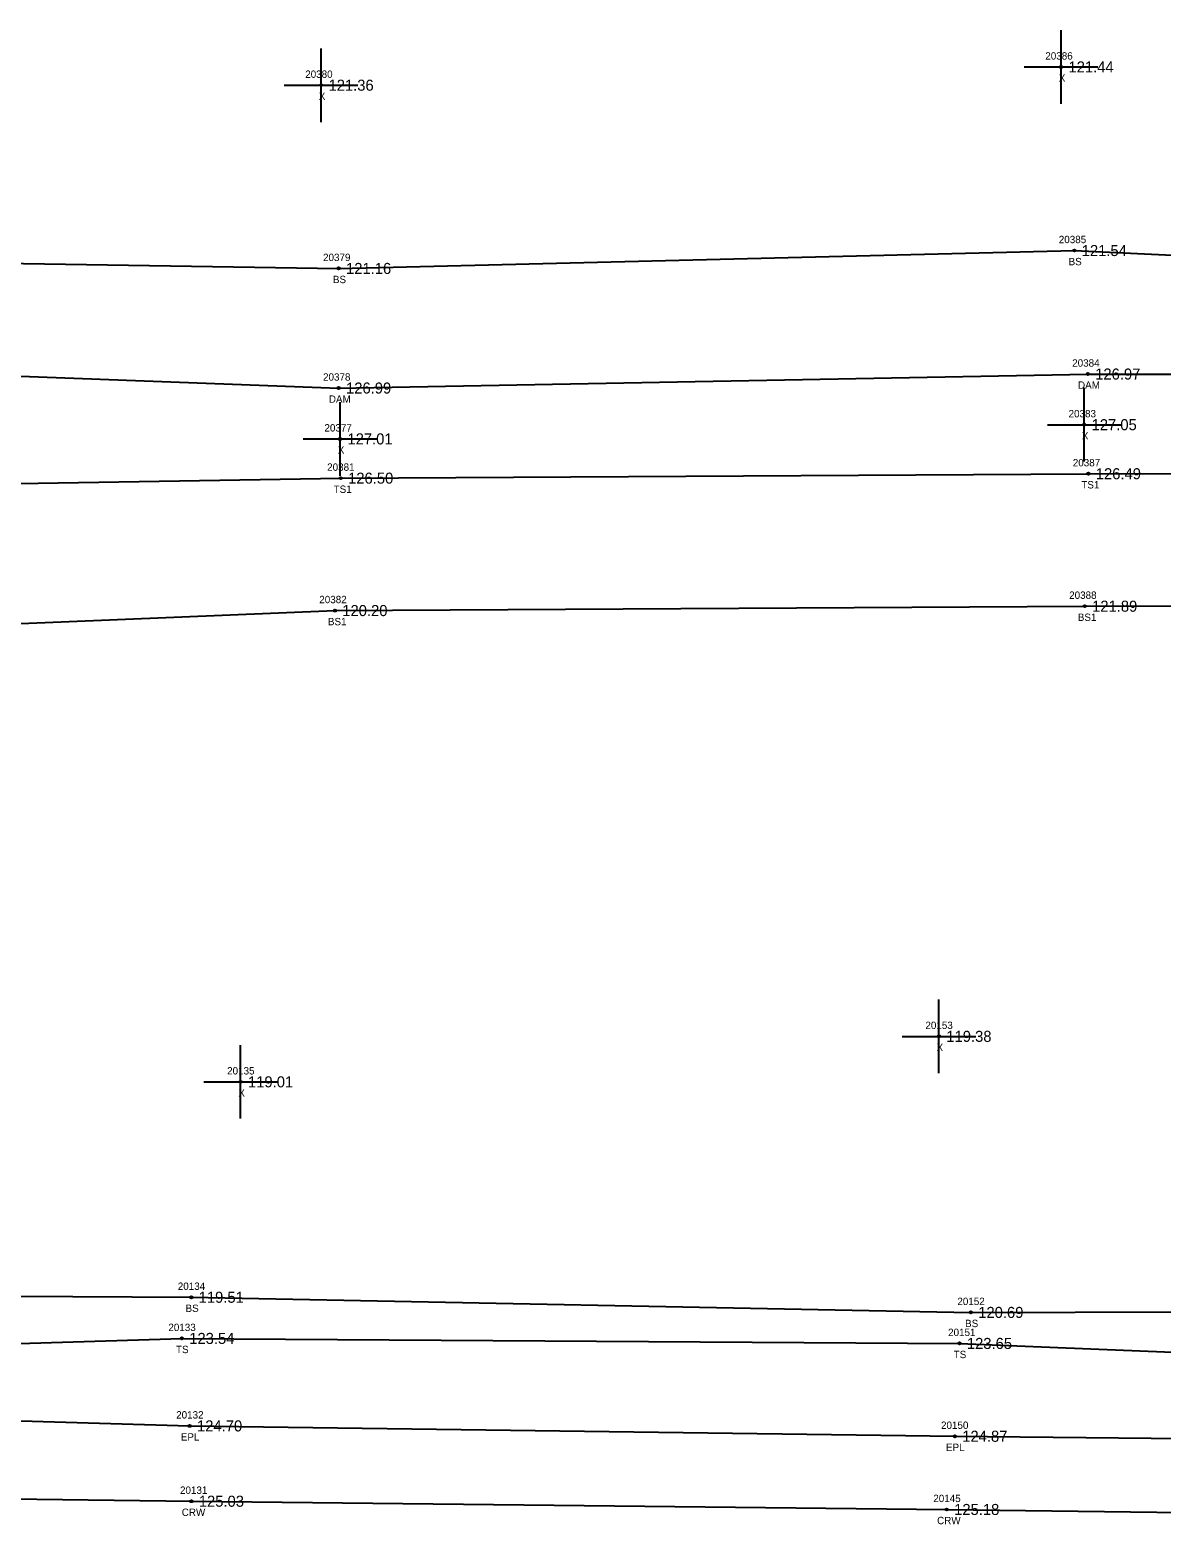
# Model space of a CAD drawing. Extents: x 2375812 to 2377225, y 1024470 to 1025135.
# Drawn here: x 2376638 to 2376791.6, y 1024920.1 to 1025124.8 of the extents above; entities that cross this region are included whole.
import ezdxf

# ---------------------------------------------------------------- set-up
doc = ezdxf.new("R2010")
doc.units = 0
for name, color, linetype in [('RD_DTM_BkLn1', 7, 'Continuous'), ('RD_DTM_BkLn2', 7, 'Continuous'), ('RD_DTM_BkLn_txCode', 7, 'Continuous'), ('RD_EX_Dam', 7, 'Continuous'), ('RD_EX_Dam_txCode', 7, 'Continuous'), ('RD_EX_Misc', 7, 'Continuous'), ('RD_EX_Misc_txCode', 7, 'Continuous'), ('RD_EX_Road', 7, 'Continuous'), ('RD_EX_Road_txCode', 7, 'Continuous'), ('RD_EX_TX_Dam_ELEV', 7, 'Continuous'), ('RD_EX_TX_Misc_ELEV', 7, 'Continuous'), ('RD_EX_TX_Road_ELEV', 7, 'Continuous'), ('RD_HC_Survey_ELEV', 7, 'Continuous'), ('RD_HC_Survey_txCode', 7, 'Continuous'), ('RD_SMD_Locator', 7, 'Continuous')]:
    doc.layers.add(name, color=color, linetype=linetype)

msp = doc.modelspace()

# ---------------------------------------------------------------- linework, layer by layer
at = {"layer": 'RD_DTM_BkLn1'}
msp.add_lwpolyline([(2376561.75, 1024926.35), (2376659.86, 1024925.07), (2376762.41, 1024923.95), (2376865.76, 1024922.65), (2376965.3, 1024921.9), (2377063.64, 1024920.86), (2377113.34, 1024920.1), (2377166.94, 1024920.12), (2377217.3, 1024921.22)], dxfattribs=at)
at = {"layer": 'RD_DTM_BkLn2'}
for points in [[(2376552.99, 1025053.79), (2376560.85, 1025063.21), (2376567.06, 1025075.76), (2376572.77, 1025085.75), (2376582.8, 1025094.03), (2376679.85, 1025092.48), (2376779.73, 1025094.91), (2376887.32, 1025089.81), (2376988.9, 1025090.57), (2377106.48, 1025091.22), (2377202.62, 1025093.89)], [(2376580.3, 1025079.96), (2376576.42, 1025074.43), (2376572.95, 1025066.08), (2376567.78, 1025062.13), (2376680.13, 1025064), (2376781.64, 1025064.6), (2376885.5, 1025064.7), (2376986.85, 1025064.56), (2377105.91, 1025065.21), (2377201.99, 1025063.63)], [(2376554.71, 1025040.88), (2376679.34, 1025046.02), (2376781.14, 1025046.61), (2376885.14, 1025046.71), (2376986.57, 1025047.57), (2377105.91, 1025056.21), (2377201.82, 1025050.7)], [(2376538.09, 1024944), (2376550.49, 1024951.37), (2376563.43, 1024953.34), (2376659.84, 1024952.77), (2376765.68, 1024950.71), (2376864.8, 1024951), (2376966.18, 1024947.81), (2377065.88, 1024945.38), (2377115.79, 1024945.18), (2377168.04, 1024944.37), (2377216.91, 1024944.34)], [(2376561.81, 1024938.95), (2376565.65, 1024944.33), (2376658.56, 1024947.18), (2376764.14, 1024946.5), (2376864.38, 1024942.41), (2376965.82, 1024942.74), (2377065.85, 1024939.54), (2377114.14, 1024940.04), (2377167.94, 1024941.05), (2377217.02, 1024940.65)]]:
    msp.add_lwpolyline(points, dxfattribs=at)
at = {"layer": 'RD_EX_Dam'}
msp.add_lwpolyline([(2376580.3, 1025079.96), (2376679.85, 1025076.24), (2376781.56, 1025078.14), (2376886.41, 1025078.13), (2376988.46, 1025077.85), (2377107.1, 1025079.69), (2377202.68, 1025079.96)], dxfattribs=at)
at = {"layer": 'RD_EX_Misc'}
for p, q in [((2376777.93, 1025114.84), (2376777.93, 1025124.84)), ((2376677.47, 1025112.36), (2376677.47, 1025122.36)), ((2376772.93, 1025119.84), (2376782.93, 1025119.84)), ((2376672.47, 1025117.36), (2376682.47, 1025117.36)), ((2376781.07, 1025066.26), (2376781.07, 1025076.26)), ((2376680.04, 1025064.33), (2376680.04, 1025074.33)), ((2376776.07, 1025071.26), (2376786.07, 1025071.26)), ((2376675.04, 1025069.33), (2376685.04, 1025069.33)), ((2376761.35, 1024983.2), (2376761.35, 1024993.2)), ((2376666.54, 1024977.02), (2376666.54, 1024987.02)), ((2376756.35, 1024988.2), (2376766.35, 1024988.2)), ((2376661.54, 1024982.02), (2376671.54, 1024982.02))]:
    msp.add_line(p, q, dxfattribs=at)
at = {"layer": 'RD_EX_Road'}
msp.add_lwpolyline([(2376561.85, 1024938.22), (2376659.62, 1024935.3), (2376763.51, 1024933.89), (2376865.73, 1024932.88), (2376965.35, 1024932.49), (2377065.13, 1024930.78), (2377114.03, 1024930.18), (2377167.22, 1024930.19), (2377217.07, 1024931.12)], dxfattribs=at)
at = {"layer": 'RD_SMD_Locator'}
for centre in [(2376777.93, 1025119.84), (2376677.47, 1025117.36), (2376779.73, 1025094.91), (2376679.85, 1025092.48), (2376781.56, 1025078.14), (2376679.85, 1025076.24), (2376781.07, 1025071.26), (2376680.04, 1025069.33), (2376781.64, 1025064.6), (2376680.13, 1025064), (2376679.34, 1025046.02), (2376781.14, 1025046.61), (2376761.35, 1024988.2), (2376666.54, 1024982.02), (2376659.84, 1024952.77), (2376765.68, 1024950.71), (2376658.56, 1024947.18), (2376764.14, 1024946.5), (2376659.62, 1024935.3), (2376763.51, 1024933.89), (2376659.86, 1024925.07), (2376762.41, 1024923.95)]:
    msp.add_circle(centre, 0.15, dxfattribs=at)

# ---------------------------------------------------------------- texts
at = {"layer": 'RD_DTM_BkLn_txCode'}
for s, p in [('20385', (2376777.62, 1025095.91)), ('20379', (2376677.73, 1025093.48)), ('BS', (2376778.95, 1025092.91)), ('BS', (2376679.07, 1025090.48)), ('20381', (2376678.29, 1025065)), ('20387', (2376779.52, 1025065.6)), ('TS1', (2376679.17, 1025062)), ('TS1', (2376780.68, 1025062.6)), ('20388', (2376779.03, 1025047.61)), ('20382', (2376677.22, 1025047.02)), ('BS1', (2376678.39, 1025044.02)), ('BS1', (2376780.2, 1025044.61)), ('20134', (2376658.01, 1024953.77)), ('20152', (2376763.85, 1024951.71)), ('BS', (2376659.06, 1024950.77)), ('20133', (2376656.73, 1024948.18)), ('20151', (2376762.59, 1024947.5)), ('BS', (2376764.9, 1024948.71)), ('TS', (2376657.77, 1024945.18)), ('TS', (2376763.35, 1024944.5))]:
    msp.add_text(s, height=1, dxfattribs=at).set_placement(p)
at = {"layer": 'RD_EX_Dam_txCode'}
for s, p in [('20384', (2376779.44, 1025079.14)), ('20378', (2376677.73, 1025077.24)), ('DAM', (2376780.23, 1025076.14)), ('DAM', (2376678.52, 1025074.24))]:
    msp.add_text(s, height=1, dxfattribs=at).set_placement(p)
at = {"layer": 'RD_EX_Misc_txCode'}
for s, p in [('20386', (2376775.79, 1025120.84)), ('20380', (2376675.31, 1025118.36)), ('X', (2376777.62, 1025117.84)), ('X', (2376677.15, 1025115.36)), ('20383', (2376778.95, 1025072.26)), ('20377', (2376677.92, 1025070.33)), ('X', (2376780.75, 1025069.26)), ('X', (2376679.73, 1025067.33)), ('20153', (2376759.51, 1024989.2)), ('X', (2376761.03, 1024986.2)), ('20135', (2376664.71, 1024983.02)), ('X', (2376666.23, 1024980.02))]:
    msp.add_text(s, height=1, dxfattribs=at).set_placement(p)
at = {"layer": 'RD_EX_Road_txCode'}
for s, p in [('20132', (2376657.79, 1024936.3)), ('20150', (2376761.63, 1024934.89)), ('EPL', (2376658.42, 1024933.3)), ('EPL', (2376762.3, 1024931.89))]:
    msp.add_text(s, height=1, dxfattribs=at).set_placement(p)
at = {"layer": 'RD_EX_TX_Dam_ELEV'}
for s, p in [('126.97', (2376782.56, 1025077.39)), ('126.99', (2376680.85, 1025075.49))]:
    msp.add_text(s, height=1.5, dxfattribs=at).set_placement(p)
at = {"layer": 'RD_EX_TX_Misc_ELEV'}
for s, p in [('121.44', (2376778.93, 1025119.09)), ('121.36', (2376678.47, 1025116.61)), ('121.54', (2376780.73, 1025094.16)), ('121.16', (2376680.85, 1025091.73)), ('127.05', (2376782.07, 1025070.51)), ('127.01', (2376681.04, 1025068.58)), ('126.50', (2376681.13, 1025063.25)), ('126.49', (2376782.64, 1025063.85)), ('120.20', (2376680.34, 1025045.27)), ('121.89', (2376782.14, 1025045.86)), ('119.38', (2376762.35, 1024987.45)), ('119.01', (2376667.54, 1024981.27)), ('119.51', (2376660.84, 1024952.02)), ('120.69', (2376766.68, 1024949.96)), ('123.54', (2376659.56, 1024946.43)), ('123.65', (2376765.14, 1024945.75))]:
    msp.add_text(s, height=1.5, dxfattribs=at).set_placement(p)
at = {"layer": 'RD_EX_TX_Road_ELEV'}
for s, p in [('124.70', (2376660.62, 1024934.55)), ('124.87', (2376764.51, 1024933.14))]:
    msp.add_text(s, height=1.5, dxfattribs=at).set_placement(p)
at = {"layer": 'RD_HC_Survey_ELEV'}
for s, p in [('125.03', (2376660.86, 1024924.32)), ('125.18', (2376763.41, 1024923.2))]:
    msp.add_text(s, height=1.5, dxfattribs=at).set_placement(p)
at = {"layer": 'RD_HC_Survey_txCode'}
for s, p in [('20131', (2376658.31, 1024926.07)), ('20145', (2376760.58, 1024924.95)), ('CRW', (2376658.55, 1024923.07)), ('CRW', (2376761.1, 1024921.95))]:
    msp.add_text(s, height=1, dxfattribs=at).set_placement(p)

doc.saveas('drawing.dxf')
